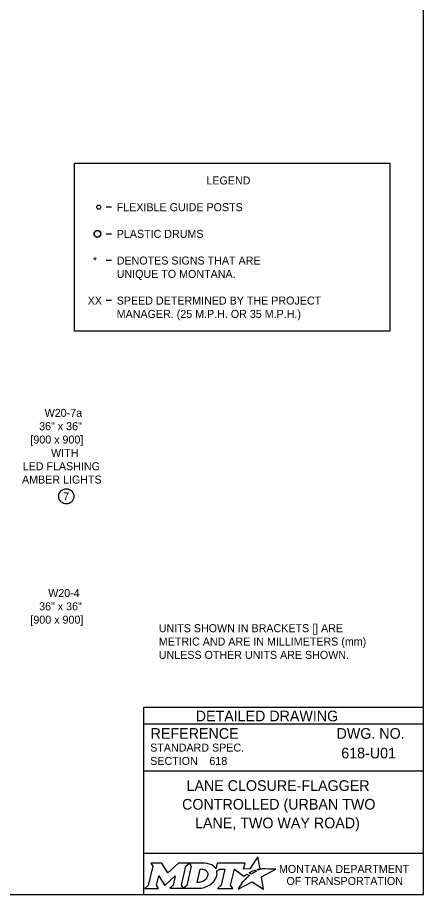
# Model space of a CAD drawing. Extents: x 49991.4 to 50021, y 49987.6 to 50011.4.
# Drawn here: x 50005.57 to 50008.61, y 50000.06 to 50006.63 of the extents above; entities that cross this region are included whole.
import ezdxf

# ---------------------------------------------------------------- set-up
doc = ezdxf.new("R2010")
doc.units = 0
doc.layers.add('Level 1', color=7, linetype='Continuous')
doc.layers.add('Level 2', color=7, linetype='Continuous')

msp = doc.modelspace()

# ---------------------------------------------------------------- linework, layer by layer
at = {"layer": 'Level 1'}
msp.add_lwpolyline([(50008.6146, 50011.2628), (50000.3356, 50011.2628), (50000.3356, 50000.0624), (50008.6146, 50000.0624)], close=True, dxfattribs=at)
for centre, radius in [((50006.1788, 50005.2128), 0.015), ((50006.1688, 50005.0128), 0.025)]:
    msp.add_circle(centre, radius, dxfattribs=at)
for start, end in [(360, 180), (180, 0)]:
    msp.add_arc((50006.1688, 50005.0128), 0.025, start, end, dxfattribs=at)
at = {"layer": 'Level 2'}
for p, q in [((50005.996, 50004.2828), (50005.996, 50005.5428)), ((50006.2738, 50005.2128), (50006.2338, 50005.2128)), ((50006.2338, 50005.0128), (50006.2738, 50005.0128)), ((50006.2738, 50004.8128), (50006.2338, 50004.8128)), ((50006.2738, 50004.5128), (50006.2338, 50004.5128)), ((50008.3627, 50004.2828), (50005.996, 50004.2828)), ((50008.6146, 50001.4624), (50006.5146, 50001.4624)), ((50006.5146, 50001.4624), (50006.5146, 50000.0624)), ((50008.6146, 50001.3374), (50006.5146, 50001.3374)), ((50008.2507, 50001.1223), (50008.2507, 50001.1223)), ((50007.0089, 50001.0629), (50007.0089, 50001.0629)), ((50008.6146, 50000.9874), (50006.5146, 50000.9874)), ((50007.5646, 50000.7383), (50007.5646, 50000.7383)), ((50008.6146, 50000.3693), (50006.5146, 50000.3693))]:
    msp.add_line(p, q, dxfattribs=at)
for points in [[(50005.996, 50005.5428), (50008.3627, 50005.5428), (50008.3627, 50004.2828)], [(50007.3771, 50000.2447), (50007.3668, 50000.2503), (50007.3784, 50000.2531), (50007.39, 50000.2551), (50007.3726, 50000.3452), (50007.3131, 50000.2539), (50007.2658, 50000.2532), (50007.2761, 50000.2973), (50007.0669, 50000.2974), (50007.0568, 50000.2549), (50007.051, 50000.2632)], [(50006.5701, 50000.2974), (50006.5842, 50000.274), (50006.5507, 50000.1307), (50006.525, 50000.1082), (50006.6266, 50000.1082), (50006.6131, 50000.131), (50006.6293, 50000.2011), (50006.673, 50000.1321), (50006.6783, 50000.1321), (50006.7534, 50000.2016), (50006.737, 50000.1305), (50006.7123, 50000.1085), (50006.8139, 50000.1085), (50006.8001, 50000.1318), (50006.8333, 50000.2742)], [(50006.8333, 50000.2742), (50006.8586, 50000.2974), (50006.7762, 50000.2974), (50006.6966, 50000.2244), (50006.6521, 50000.2971), (50006.5701, 50000.2974)], [(50006.9722, 50000.2974), (50006.8586, 50000.2974), (50006.8733, 50000.2745), (50006.8394, 50000.1307), (50006.8139, 50000.1085), (50006.9245, 50000.1085)], [(50007.2527, 50000.1479), (50007.2374, 50000.1235), (50007.2327, 50000.116), (50007.2269, 50000.1074), (50007.2246, 50000.1031), (50007.3299, 50000.1562), (50007.4138, 50000.1011), (50007.4007, 50000.1938), (50007.5076, 50000.2522), (50007.4583, 50000.253), (50007.4282, 50000.2534), (50007.4074, 50000.2537), (50007.4006, 50000.2522), (50007.3957, 50000.251), (50007.3873, 50000.2487), (50007.3771, 50000.2447)], [(50006.9962, 50000.2107), (50006.995, 50000.2026), (50006.9918, 50000.1933), (50006.9876, 50000.1851), (50006.982, 50000.1776), (50006.9755, 50000.1707), (50006.9676, 50000.1644), (50006.9593, 50000.1597), (50006.9502, 50000.1558), (50006.9411, 50000.1535), (50006.9319, 50000.1526), (50006.916, 50000.1526), (50006.9396, 50000.2526), (50006.9556, 50000.2526), (50006.9632, 50000.252), (50006.9708, 50000.2501), (50006.9774, 50000.2471), (50006.9835, 50000.2429), (50006.9883, 50000.2379), (50006.992, 50000.2319), (50006.9947, 50000.2257), (50006.9963, 50000.2183), (50006.9963, 50000.2153), (50006.9962, 50000.2107)], [(50007.0636, 50000.2383), (50007.0882, 50000.2514), (50007.1251, 50000.2514), (50007.0965, 50000.1309), (50007.069, 50000.1082), (50007.1852, 50000.1082), (50007.1682, 50000.1311), (50007.1964, 50000.2513), (50007.2677, 50000.1996), (50007.2888, 50000.2147), (50007.3085, 50000.2038)], [(50007.3267, 50000.2171), (50007.3243, 50000.2154), (50007.306, 50000.225), (50007.3163, 50000.2307), (50007.3204, 50000.2329), (50007.329, 50000.2369), (50007.3347, 50000.2395), (50007.3426, 50000.2425), (50007.3499, 50000.2452), (50007.3617, 50000.2378), (50007.3577, 50000.2357), (50007.3531, 50000.2332), (50007.3489, 50000.231), (50007.3439, 50000.2281), (50007.342, 50000.227), (50007.3393, 50000.2254), (50007.3368, 50000.224), (50007.3345, 50000.2224), (50007.3319, 50000.2206), (50007.3292, 50000.2188), (50007.3267, 50000.2171)], [(50006.9702, 50000.1158), (50006.9786, 50000.1184), (50006.9916, 50000.1238), (50007.012, 50000.1348)], [(50007.2666, 50000.164), (50007.2666, 50000.164)]]:
    msp.add_lwpolyline(points, dxfattribs=at)
msp.add_circle((50005.9358, 50003.0457), 0.0569, dxfattribs=at)
for centre, radius, start, end in [((50006.9513, 50000.2363), 0.1183, 300.91025, 339.13831), ((50006.9953, 50000.219), 0.0709, 339.53292, 15.85821)]:
    msp.add_arc(centre, radius, start, end, dxfattribs=at)
for centre, major_axis, ratio, start_param, end_param in [((50006.9701, 50000.25), (0.0834, -0.0037), 0.568097, 0.61298, 1.570796), ((50007.0257, 50000.2573), (0.0361, -0.0295), 0.469099, 1.225588, 1.570796), ((50007.2974, 50000.1941), (-0.0112, -0.0097), 0.021651, 3.157348, 6.283185), ((50007.2597, 50000.1559), (-0.00694, -0.00806), 0.008222, 0, 3.137361), ((50007.2764, 50000.1742), (-0.0098, -0.0102), 0.016458, 3.141593, 6.279097), ((50006.9248, 50000.2568), (0, 0.1484), 0.987302, 3.139398, 3.456847)]:
    msp.add_ellipse(centre, major_axis=major_axis, ratio=ratio, start_param=start_param, end_param=end_param, dxfattribs=at)

# ---------------------------------------------------------------- texts
for s, height, p in [('LEGEND', 0.06, (50006.9866, 50005.3828)), ('FLEXIBLE GUIDE POSTS', 0.06, (50006.3138, 50005.1828)), ('PLASTIC DRUMS', 0.06, (50006.3138, 50004.9828)), ('*', 0.06, (50006.1352, 50004.7828)), ('DENOTES SIGNS THAT ARE', 0.06, (50006.3138, 50004.7828)), ('UNIQUE TO MONTANA.', 0.06, (50006.3138, 50004.6828)), ('XX', 0.06, (50006.096, 50004.4828)), ('SPEED DETERMINED BY THE PROJECT', 0.06, (50006.3138, 50004.4828)), ('MANAGER. (25 M.P.H. OR 35 M.P.H.)', 0.06, (50006.3138, 50004.3828)), ('W20-7a', 0.06, (50005.7734, 50003.6414)), ('36" x 36"', 0.06, (50005.7319, 50003.5414)), ('[900 x 900]', 0.06, (50005.6664, 50003.4414)), ('WITH ', 0.06, (50005.8213, 50003.3414)), ('LED FLASHING', 0.06, (50005.6085, 50003.2414)), ('AMBER LIGHTS', 0.06, (50005.6035, 50003.1414)), ('7', 0.06, (50005.912, 50003.0157)), ('W20-4', 0.06, (50005.8, 50002.2914)), ('36" x 36"', 0.06, (50005.7319, 50002.1914)), ('[900 x 900]', 0.06, (50005.6664, 50002.0914)), ('UNITS SHOWN IN BRACKETS [] ARE ', 0.06, (50006.6294, 50002.0278)), ('METRIC AND ARE IN MILLIMETERS (mm) ', 0.06, (50006.6294, 50001.9278)), ('UNLESS OTHER UNITS ARE SHOWN.', 0.06, (50006.6294, 50001.8278)), ('DETAILED DRAWING', 0.0799, (50006.9063, 50001.3599)), ('REFERENCE', 0.08, (50006.5682, 50001.229)), ('DWG. NO.', 0.08, (50007.9624, 50001.229)), ('STANDARD SPEC.', 0.06, (50006.5649, 50001.133)), ('618-U01', 0.08, (50007.9979, 50001.0823)), ('SECTION', 0.06, (50006.5649, 50001.033)), ('618', 0.06, (50007.0089, 50001.0329)), ('LANE CLOSURE-FLAGGER', 0.08, (50006.8372, 50000.8383)), ('CONTROLLED (URBAN TWO', 0.08, (50006.8041, 50000.6983)), ('LANE, TWO WAY ROAD)', 0.08, (50006.9011, 50000.5583)), ('MONTANA DEPARTMENT', 0.06, (50007.5308, 50000.2236)), ('OF TRANSPORTATION', 0.06, (50007.587, 50000.1336))]:
    msp.add_text(s, height=height, dxfattribs=at).set_placement(p)

doc.saveas('drawing.dxf')
